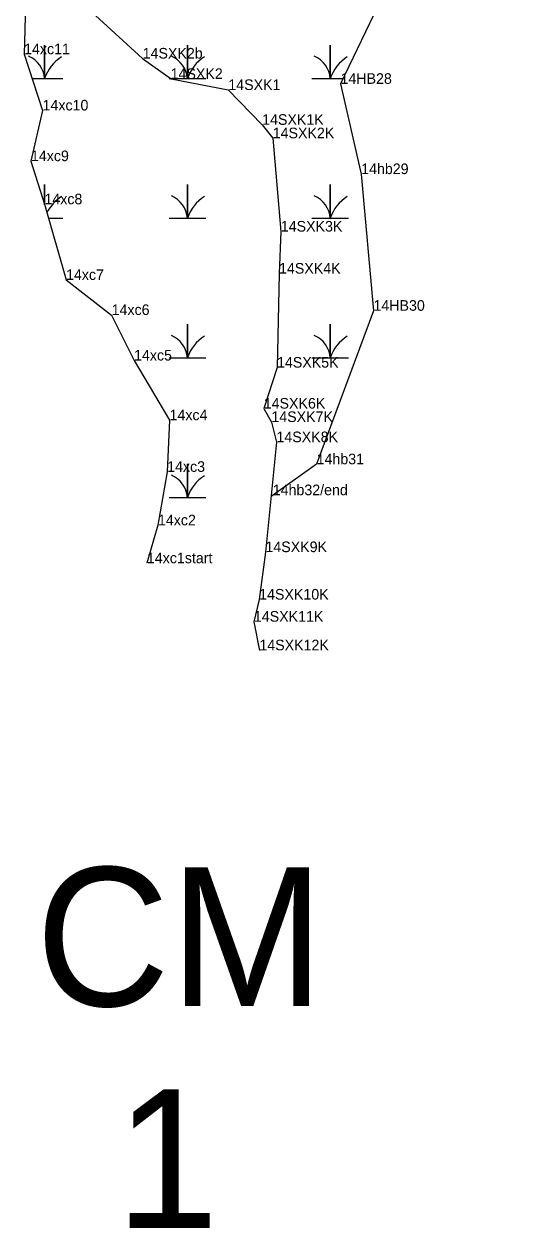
# Model space of a CAD drawing. Extents: x 2072529 to 2268796, y 436423 to 470406.
# Drawn here: x 2253780 to 2254011, y 442555 to 443122 of the extents above; entities that cross this region are included whole.
import ezdxf

# ---------------------------------------------------------------- set-up
doc = ezdxf.new("R2010")
doc.units = 0
for name, color, linetype in [('Default', 7, 'Continuous'), ('Exist Environmental Wetland Boundary', 7, 'Continuous'), ('Exist Environmental Wetland Boundary Cogo Comment', 7, 'Continuous'), ('Exist Hydro Jurisdictional Stream or Body of Water NEU Mitigable', 7, 'Continuous'), ('Exist Hydro Jurisdictional Stream or Body of Water NEU Mitigable Cogo Comment', 7, 'Continuous'), ('Exist Hydro Swamp or Marsh', 7, 'Continuous'), ('Old_Level_20', 7, 'Continuous')]:
    doc.layers.add(name, color=color, linetype=linetype)

msp = doc.modelspace()

# ---------------------------------------------------------------- linework, layer by layer
at = {"layer": 'Exist Environmental Wetland Boundary'}
for points in [[(2254016.44, 443436.8), (2253980.84, 443407.93), (2253969.11, 443329.26), (2253933.2, 443297.83), (2253950.65, 443241.78), (2253964.42, 443201.58), (2253960.36, 443159.47), (2253928.92, 443094), (2253938.65, 443051.47), (2253944.44, 442987.07), (2253917.67, 442914.74), (2253896.2, 442899.57)], [(2253780.68, 443131.44), (2253779.94, 443107.95), (2253788.65, 443081.45), (2253783.18, 443057.57), (2253789.53, 443037.25), (2253799.69, 443001.59), (2253821.17, 442985.07), (2253831.72, 442963.63), (2253848.44, 442935.49), (2253847.31, 442911.16), (2253842.97, 442885.97), (2253837.77, 442868.1)]]:
    msp.add_lwpolyline(points, dxfattribs=at)
at = {"layer": 'Exist Hydro Jurisdictional Stream or Body of Water NEU Mitigable'}
msp.add_lwpolyline([(2253806.17, 443133.02), (2253835.76, 443105.92), (2253849.13, 443096.34), (2253876.1, 443091.1), (2253892.03, 443074.69), (2253897, 443068.35), (2253900.82, 443024.39), (2253899.97, 443004.58), (2253899.02, 442960.29), (2253892.78, 442940.98), (2253896.37, 442934.65), (2253898.76, 442925.15), (2253893.58, 442873.35), (2253890.62, 442850.98), (2253888.14, 442840.57), (2253890.71, 442827.06)], dxfattribs=at)
at = {"layer": 'Exist Hydro Swamp or Marsh'}
for points in [[(2253783.7, 443096.52), (2253789.59, 443096.52), (2253789.59, 443112.3), (2253789.59, 443096.52), (2253798.19, 443096.52)], [(2253848.24, 443096.52), (2253856.84, 443096.52), (2253856.84, 443112.3), (2253856.84, 443096.52), (2253865.44, 443096.52)], [(2253915.49, 443096.52), (2253924.09, 443096.52), (2253924.09, 443112.3), (2253924.09, 443096.52), (2253930.13, 443096.52)], [(2253789.59, 443037.04), (2253789.59, 443046.5), (2253789.59, 443037.04)], [(2253848.24, 443030.72), (2253856.84, 443030.72), (2253856.84, 443046.5), (2253856.84, 443030.72), (2253865.44, 443030.72)], [(2253915.49, 443030.72), (2253924.09, 443030.72), (2253924.09, 443046.5), (2253924.09, 443030.72), (2253932.69, 443030.72)], [(2253791.39, 443030.72), (2253798.19, 443030.72)], [(2253848.24, 442964.92), (2253856.84, 442964.92), (2253856.84, 442980.7), (2253856.84, 442964.92), (2253865.44, 442964.92)], [(2253915.49, 442964.92), (2253924.09, 442964.92), (2253924.09, 442980.7), (2253924.09, 442964.92), (2253932.69, 442964.92)], [(2253848.24, 442899.12), (2253856.84, 442899.12), (2253856.84, 442914.9), (2253856.84, 442899.12), (2253865.44, 442899.12)]]:
    msp.add_lwpolyline(points, dxfattribs=at)
for centre, radius, start, end in [((2253777.32, 443095.63), 12.3, 4.1403, 67.535), ((2253807.83, 443090.46), 19.22, 122.1274, 161.6222), ((2253844.57, 443095.63), 12.3, 4.1403, 67.535), ((2253875.08, 443090.46), 19.22, 122.1274, 161.6222), ((2253911.82, 443095.63), 12.3, 4.1403, 67.535), ((2253942.33, 443090.46), 19.22, 122.1274, 161.6222), ((2253807.83, 443024.66), 19.22, 122.1274, 153.3155), ((2253844.57, 443029.83), 12.3, 4.1403, 67.535), ((2253875.08, 443024.66), 19.22, 122.1274, 161.6222), ((2253911.82, 443029.83), 12.3, 4.1403, 67.535), ((2253942.33, 443024.66), 19.22, 122.1274, 161.6222), ((2253844.57, 442964.03), 12.3, 4.1403, 67.535), ((2253875.08, 442958.86), 19.22, 122.1274, 161.6222), ((2253911.82, 442964.03), 12.3, 4.1403, 67.535), ((2253942.33, 442958.86), 19.22, 122.1274, 161.6222), ((2253844.57, 442898.23), 12.3, 4.1403, 67.535), ((2253875.08, 442893.06), 19.22, 122.1274, 161.6222)]:
    msp.add_arc(centre, radius, start, end, dxfattribs=at)
at = {"layer": 'Old_Level_20'}
for p, q in [((2253779.94, 443107.95), (2253779.94, 443107.95)), ((2253835.76, 443105.92), (2253835.76, 443105.92)), ((2253849.13, 443096.34), (2253849.13, 443096.34)), ((2253928.92, 443094), (2253928.92, 443094)), ((2253876.1, 443091.1), (2253876.1, 443091.1)), ((2253788.65, 443081.45), (2253788.65, 443081.45)), ((2253892.03, 443074.69), (2253892.03, 443074.69)), ((2253897, 443068.35), (2253897, 443068.35)), ((2253783.18, 443057.57), (2253783.18, 443057.57)), ((2253938.65, 443051.47), (2253938.65, 443051.47)), ((2253789.53, 443037.25), (2253789.53, 443037.25)), ((2253900.82, 443024.39), (2253900.82, 443024.39)), ((2253899.97, 443004.58), (2253899.97, 443004.58)), ((2253799.69, 443001.59), (2253799.69, 443001.59)), ((2253944.44, 442987.07), (2253944.44, 442987.07)), ((2253821.17, 442985.07), (2253821.17, 442985.07)), ((2253831.72, 442963.63), (2253831.72, 442963.63)), ((2253899.02, 442960.29), (2253899.02, 442960.29)), ((2253892.78, 442940.98), (2253892.78, 442940.98)), ((2253848.44, 442935.49), (2253848.44, 442935.49)), ((2253896.37, 442934.65), (2253896.37, 442934.65)), ((2253898.76, 442925.15), (2253898.76, 442925.15)), ((2253917.67, 442914.74), (2253917.67, 442914.74)), ((2253847.31, 442911.16), (2253847.31, 442911.16)), ((2253897.03, 442900.16), (2253897.03, 442900.16)), ((2253842.97, 442885.97), (2253842.97, 442885.97)), ((2253893.58, 442873.35), (2253893.58, 442873.35)), ((2253837.77, 442868.1), (2253837.77, 442868.1)), ((2253890.62, 442850.98), (2253890.62, 442850.98)), ((2253888.14, 442840.57), (2253888.14, 442840.57)), ((2253890.71, 442827.06), (2253890.71, 442827.06))]:
    msp.add_line(p, q, dxfattribs=at)

# ---------------------------------------------------------------- texts
at = {"layer": 'Default'}
for s, p in [('CM', (2253785.38, 442659.45)), ('CM', (2253785.38, 442659.45)), ('CM', (2253785.38, 442659.45)), ('1', (2253823.03, 442554.91)), ('1', (2253823.03, 442554.91)), ('1', (2253823.03, 442554.91))]:
    msp.add_text(s, height=65.34, dxfattribs=at).set_placement(p)
at = {"layer": 'Exist Environmental Wetland Boundary Cogo Comment'}
for s, p in [('14xc11', (2253779.94, 443107.95)), ('14xc10', (2253788.65, 443081.45)), ('14xc9', (2253783.18, 443057.57)), ('14hb29', (2253938.65, 443051.47)), ('14xc8', (2253789.53, 443037.25)), ('14xc7', (2253799.69, 443001.59)), ('14HB30', (2253944.44, 442987.07)), ('14xc6', (2253821.17, 442985.07)), ('14xc5', (2253831.72, 442963.63)), ('14xc4', (2253848.44, 442935.49)), ('14hb31', (2253917.67, 442914.74)), ('14xc3', (2253847.31, 442911.16)), ('14hb32/end', (2253897.02, 442900.17)), ('14xc2', (2253842.97, 442885.97)), ('14xc1start', (2253837.77, 442868.1))]:
    msp.add_text(s, height=5, dxfattribs=at).set_placement(p)
at = {"layer": 'Exist Hydro Jurisdictional Stream or Body of Water NEU Mitigable Cogo Comment'}
for s, p in [('14SXK2b', (2253835.76, 443105.92)), ('14SXK2', (2253848.93, 443096.29)), ('14SXK1', (2253876.1, 443091.1)), ('14HB28', (2253928.92, 443094)), ('14SXK1K', (2253892.03, 443074.69)), ('14SXK2K', (2253897, 443068.35)), ('14SXK3K', (2253900.82, 443024.39)), ('14SXK4K', (2253899.97, 443004.58)), ('14SXK5K', (2253899.02, 442960.29)), ('14SXK6K', (2253892.78, 442940.98)), ('14SXK7K', (2253896.37, 442934.65)), ('14SXK8K', (2253898.76, 442925.15)), ('14SXK9K', (2253893.58, 442873.35)), ('14SXK10K', (2253890.62, 442850.98)), ('14SXK11K', (2253888.14, 442840.57)), ('14SXK12K', (2253890.71, 442827.06))]:
    msp.add_text(s, height=5, dxfattribs=at).set_placement(p)

doc.saveas('drawing.dxf')
